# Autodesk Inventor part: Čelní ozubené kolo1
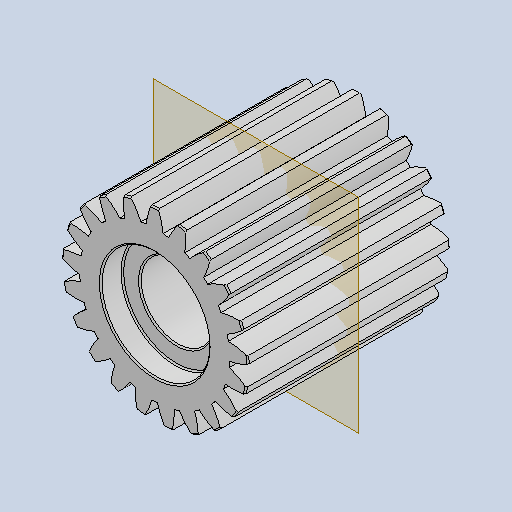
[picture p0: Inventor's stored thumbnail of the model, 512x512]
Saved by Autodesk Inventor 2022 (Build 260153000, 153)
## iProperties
CustomPartVersion: 1
Created: 2025-05
Part Number: Čelní ozubené kolo1
Material: Všeobecné
Document SubType Name: Modeling
Designer: jbart
Categories: <?xml version="1.0" encoding="UTF-16"?> <MemberInstance><Categories><FamilyTemplate><FamilyTemplateParameter ValueType="xs:double" Id="1" ObjectReferenceKey="da
Density: 1 g/cm^3
Appearance: Výchozí
Mass: 1423.69 g
Surface Area: 1668.6 cm^2
Volume: 1423.69 cm^3
Author: jbart
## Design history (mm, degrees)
sketch "Sketch1"
  geometry: C1 r 68.996 at (0, 0)
  constraints: 1 centre point
  dimensions: "d0" = 137.99216 diameter of C1 (= da_da)
extrude "Extrusion1" new body sketch "Sketch1" distance "d1" = 150 (= da_b); taper "d2" = 0 deg
workplane "Work Plane2"
sketch "Sketch2"
  geometry: C1 r 68.996 at (0, 0) reference; C2 r 63 at (0, 0)
  constraints: 1 centre point, 1 coincident
  dimensions: "d3" = 126 diameter of C2 (= da_d)
feature "Roztečný průměr" sketch "Sketch2" dims "d4" = 10, "d5" = 0
workplane "Work Plane8"
workplane "Work Plane9"
feature "Čelní ozubené kolo" dims "da_b" = 150, "da_d" = 126, "da_aw" = 366.61846, "da_da" = 137.99216, "da_df" = 111, "da_dw" = 126.21291, angle "da_beta" = 0 deg, "da_lefttooth" = 0, "da_righttooth" = 0
sketch "Náčrt3"
  geometry: C1 r 40 at (0, 0); 1 further point
  constraints: 1 centre point, 1 coincident
  dimensions: "d49" = 80 diameter of C1
extrude "Vysunutí2" cut sketch "Náčrt3" distance "d50" = 16; taper "d51" = 0 deg
fillet "Zaoblení1" dims "d52" = 1
chamfer "Zkosení1" distance "d53" = 1; stored, may be unused: second distance "d54" = 2, angle "d55" = 45 deg
sketch "Náčrt4"
  geometry: C1 r 27 at (0, 0); 1 further point
  constraints: 1 centre point, 1 coincident
  dimensions: "d56" = 54 diameter of C1
node "Pracovní rovina11"
extrude "Vysunutí4" cut sketch "Náčrt4" extent not by distance; stored distance "d63" = 0; taper "d64" = 0 deg
mirror "Zrcadlit2"
fillet "Zaoblení2" dims "d65" = 1
chamfer "Zkosení3" distance "d66" = 1; stored, may be unused: second distance "d67" = 2, angle "d68" = 45 deg
chamfer "Zkosení4" distance "d69" = 1; stored, may be unused: second distance "d70" = 2, angle "d71" = 45 deg
chamfer "Zkosení5" distance "d72" = 1; stored, may be unused: second distance "d73" = 2, angle "d74" = 45 deg
body "Solid1"
body "Srf1"
other parameters: "d16" = 366.61846 (= da_aw), "d17" = 0, "d34" = 1.496 (computed from da_z), "d39" = 0, "d41" = 0, "d43" = 366.61846 (= da_aw), "d46" = 366.61846 (= da_aw), "d47" = 0, "d48" = 0, "d62" = -75
